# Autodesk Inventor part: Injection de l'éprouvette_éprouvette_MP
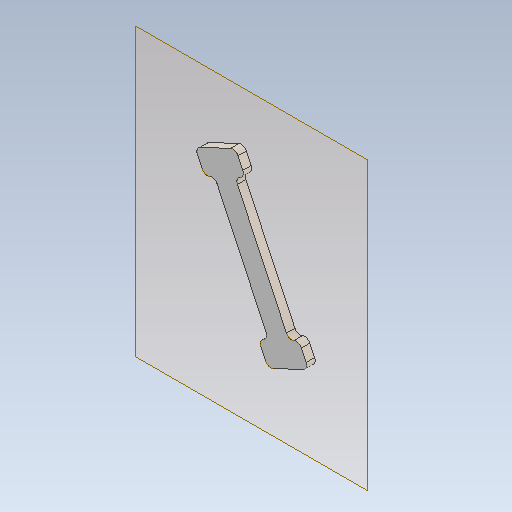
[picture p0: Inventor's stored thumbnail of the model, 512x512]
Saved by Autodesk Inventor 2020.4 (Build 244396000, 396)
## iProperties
Created: 2021-10
Part Number: Injection de l'éprouvette_éprouvette_MP
Material: Générique
Document SubType Name: Modeling
Designer: mel
Density: 1 g/cm^3
Appearance: Par défaut
Author: mel
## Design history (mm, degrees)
derived "éprouvette.ipt"
node "Plan de construction1"
node "Injection de l'éprouvette_éprouvette_WP"
node "Plan de construction2"
sketch "Esquisse2"
  geometry: L1 (28.902, -34.154)-(28.902, 67.846); L2 (28.902, 67.846)-(-53.598, 67.846); L3 (-53.598, 67.846)-(-53.598, -34.154); L4 (-53.598, -34.154)-(28.902, -34.154); L5 (0, 0)-(-17.457, 37.098) reference; L6 (-15.541, 42.42)-(-17.244, 46.04) reference; L7 (-19.905, 46.998)-(-30.763, 41.888) reference; L8 (-31.721, 39.227)-(-30.018, 35.608) reference; L9 (-24.696, 33.692)-(-7.239, -3.406) reference; L10 (-9.155, -8.729)-(-7.452, -12.348) reference; L11 (-4.79, -13.306)-(6.067, -8.197) reference; L12 (7.026, -5.535)-(5.322, -1.916) reference; A1 r 2 centre (-15.647, 37.949) between (-16.499, 39.759) and (-17.457, 37.098) reference; A2 r 2 centre (-17.35, 41.569) between (-16.499, 39.759) and (-15.541, 42.42) reference; A3 r 2 centre (-19.054, 45.188) between (-17.244, 46.04) and (-19.905, 46.998) reference; A4 r 2 centre (-29.911, 40.079) between (-30.763, 41.888) and (-31.721, 39.227) reference; A5 r 2 centre (-28.208, 36.459) between (-30.018, 35.608) and (-27.357, 34.65) reference; A6 r 2 centre (-26.505, 32.84) between (-24.696, 33.692) and (-27.357, 34.65) reference; A7 r 2 centre (-9.048, -4.258) between (-8.197, -6.067) and (-7.239, -3.406) reference; A8 r 2 centre (-7.345, -7.877) between (-8.197, -6.067) and (-9.155, -8.729) reference; A9 r 2 centre (-5.642, -11.496) between (-7.452, -12.348) and (-4.79, -13.306) reference; A10 r 2 centre (5.216, -6.387) between (6.067, -8.197) and (7.026, -5.535) reference; A11 r 2 centre (3.513, -2.768) between (5.322, -1.916) and (2.661, -0.958) reference; A12 r 2 centre (1.81, 0.852) between (0, 0) and (2.661, -0.958) reference; 1 further point
  constraints: 8 end point
  dimensions: "d15" = 41.25 horizontal distance of point (-12.348, 16.846) L1.end (= 1.5 x Xmax); "d16" = 51 vertical distance of point (-12.348, 16.846) L1.end (= 1.5 x Ymax); "d17" = 41.25 horizontal distance of point (-12.348, 16.846) L2.end (= -1.5 x Xmin); "d18" = 51 vertical distance of point (-12.348, 16.846) L2.end (= 1.5 x Ymax); "d19" = 41.25 horizontal distance of point (-12.348, 16.846) L3.end (= -1.5 x Xmin); "d20" = 51 vertical distance of point (-12.348, 16.846) L3.end (= -1.5 x Ymin); "d21" = 41.25 horizontal distance of point (-12.348, 16.846) L1.start (= 1.5 x Xmax); "d22" = 51 vertical distance of point (-12.348, 16.846) L1.start (= -1.5 x Ymin)
feature "Carreau délimité2" sketch "Esquisse2"
feature "Séparation d'empreinte2"
feature "Solide1::éprouvette.ipt"
tag "FonctionRepérage1"
feature "Solide2::Injection de l'éprouvette_éprouvette_WP"
tag "FonctionRepérage3"
body "Srf2"
node "Solide6"
node "Solide7"
node "Solide1"
feature "éprouvette.ipt_Corps"
node "Solide5"
feature "Injection de l'éprouvette_éprouvette_WP_Corps"
other parameters: "d7" = -25, "d8" = 27.5, "d9" = 27.5, "d10" = 34, "d11" = 34, "d13" = 0, "Xmin" = -27.5, "Ymin" = -34, "Zmin" = -25, "Xmax" = 27.5, "Ymax" = 34, "Zmax" = 25
